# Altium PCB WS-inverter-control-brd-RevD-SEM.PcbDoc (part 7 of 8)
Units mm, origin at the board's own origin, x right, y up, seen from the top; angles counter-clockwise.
Board outline 270 x 105.92 mm, 6 copper layers (Top Layer, Int1 (Sign), Int2 (PWR), Int3 (GND), Int4 (Sign), Bottom Layer), stack 1.509 mm thick; 709 components, 375 nets, 2377 pads, 1332 vias.
Unrouted connection lines stored in the file: 55.
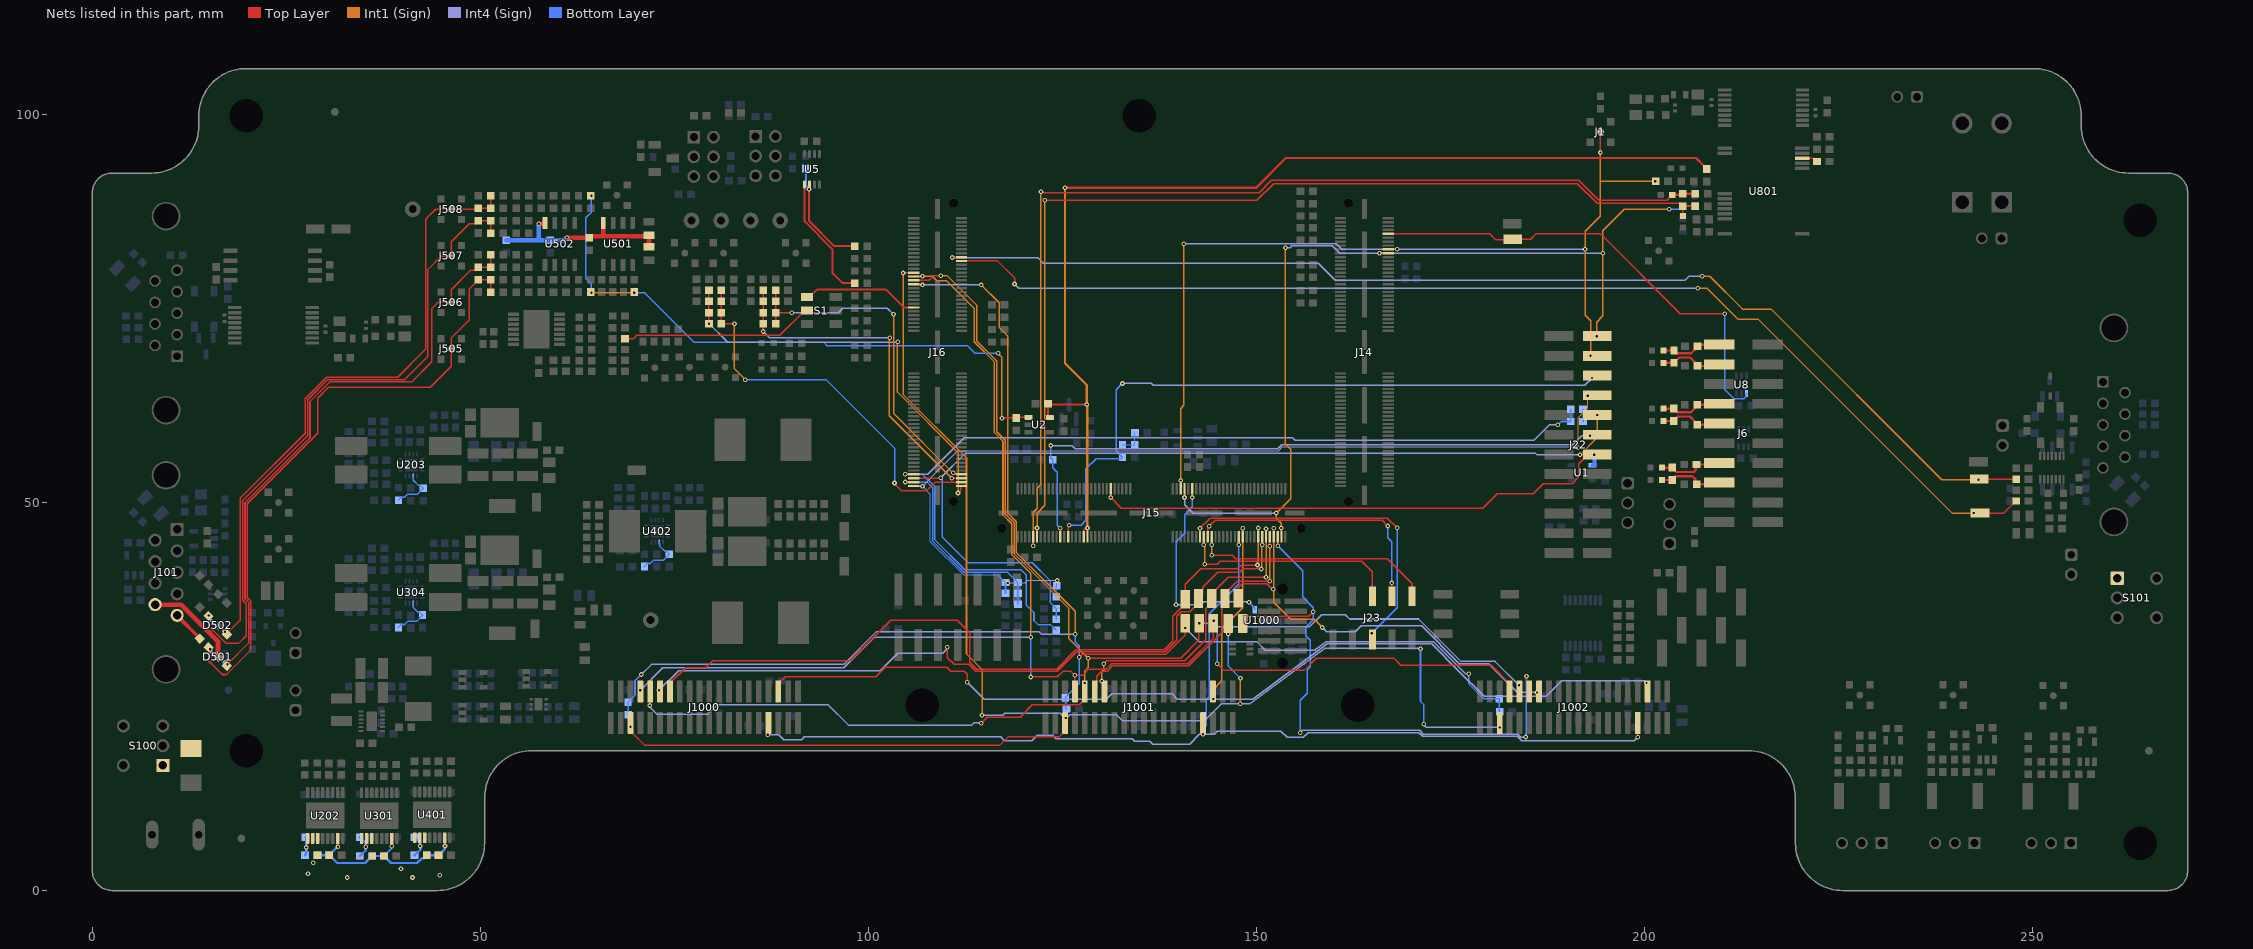
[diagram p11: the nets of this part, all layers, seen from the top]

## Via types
v1: diameter 0.6, hole 0.3, Top Layer to Bottom Layer, tented both sides, 1302 vias
v2: diameter 0.5, hole 0.2, Top Layer to Bottom Layer, 17 vias
v3: diameter 0.6, hole 0.3, Top Layer to Bottom Layer, 12 vias
v4: diameter 0.8, hole 0.5, Top Layer to Bottom Layer, tented both sides, 1 vias

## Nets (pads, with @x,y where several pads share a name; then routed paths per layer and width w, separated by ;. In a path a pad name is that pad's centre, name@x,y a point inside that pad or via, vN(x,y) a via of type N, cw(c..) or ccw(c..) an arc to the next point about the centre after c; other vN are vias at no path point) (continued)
Power_EN_HS: J15.23 J1000.36 J1001.36 J1002.36 | length 148.5
  Top Layer w0.18: J1000.36@88.399,25.653 88.399,26.681 89.265,27.546 100.953,27.546 102.197,28.79 110.09,28.79 110.633,28.246 112.333,28.246 112.741,27.838 v1(112.741,26.818) ; J1001.36@144.399,25.653 144.399,24.699 v1(144.422,24.676) ; J15.23@148.233,45.585 v1(148.233,46.67) ; v1(200.256,26.736) J1002.36@200.337,26.655
  Int1 (Sign) w0.18: v1(144.422,24.676) 144.422,25.899 145.543,27.021 145.543,33.726 148.233,36.416 v1(148.233,46.67)
  Int4 (Sign) w0.18: v1(112.741,26.818) 112.762,26.818 114.943,24.636 130.637,24.636 131.337,25.336 139.143,25.336 139.803,24.676 v1(144.422,24.676) 149.511,24.676 159.108,31.776 172.593,31.776 176.023,28.346 176.033,28.346 179.364,25.016 187.348,25.016 189.368,27.036 199.956,27.036 v1(200.256,26.736)
Power_EN_LoadSW: R237.1 R241.2 R302.1 R306.2 R405.1 R417.2 U202.7 U301.7 U401.7 | length 24.6
  Top Layer w0.2: v1@31.634,5.646 v1(31.643,5.636) ; U202.7@31.634,6.113 31.659,6.138 U202.7@31.661,6.138 ; U401.7@45.425,6.793 U401.7@45.434,6.784 ; v1@45.434,5.745 v1(45.443,5.736)
  Top Layer w0.3: v1@31.634,5.646 U202.7@31.634,6.113 ; v1(38.583,5.686) U301.7@38.582,6.693 ; v1@45.434,5.745 U401.7@45.434,6.784
  Bottom Layer w0.2: R306.2@37.568,4.443 37.593,4.443 38.583,5.432 v1(38.583,5.686)
  Bottom Layer w0.3: R237.1@29,4.563 R241.2@30.525,4.563 ; v1(31.643,5.636) 31.598,5.636 R241.2@30.525,4.563 ; R306.2@37.568,4.443 R302.1@36.068,4.443 36.043,4.443 35.137,3.536 31.551,3.536 R241.2@30.525,4.563 ; R306.2@37.593,4.443 38.5,3.536 41.843,3.536 42.477,4.17 42.727,4.17 R405.1@43.1,4.543 44.625,4.543 45.386,5.304 45.386,5.679 v1(45.443,5.736)
Power_EN_LS: J15.25 J1000.33 J1001.33 J1002.33 | length 147.6
  Top Layer w0.18: v1(87.045,20.066) 87.045,21.505 J1000.33@87.129,21.588 ; v1(143.116,20.134) 143.129,20.147 J1001.33@143.129,21.588 ; J15.25@147.733,45.585 147.738,45.58 147.738,44.541 v1(147.743,44.536) ; J1002.33@199.129,21.588 199.143,21.574 v1(199.143,19.736)
  Int4 (Sign) w0.18: v1(87.045,20.066) 88.477,20.066 89.091,19.451 91.417,19.451 91.762,19.796 117.05,19.796 117.53,19.316 121.033,19.316 121.728,20.011 123.788,20.011 124.234,19.565 134.015,19.565 134.343,19.236 136.252,19.236 136.619,18.869 141.386,18.869 142.651,20.134 v1(143.116,20.134) 144.541,20.134 144.954,20.547 153.133,20.547 153.943,19.736 156.043,19.736 156.655,20.348 170.94,20.348 171.411,19.876 183.581,19.876 184.184,19.273 198.68,19.273 v1(199.143,19.736)
  Bottom Layer w0.18: v1(143.116,20.134) 143.116,20.903 143.512,21.3 143.512,24.505 143.945,24.938 143.945,35.676 147.743,39.475 v1(147.743,44.536)
Power_Good: J15.50 U1000.4 | length 26.7
  Top Layer w0.18: v1(141.733,50.653) J15.50@141.733,51.757
  Int4 (Sign) w0.18: v1(139.643,36.836) 142.795,36.836 143.195,37.236 148.83,37.236 148.93,37.136 v1(149.043,37.136)
  Bottom Layer w0.18: v1(139.643,36.836) 139.643,44.959 140.743,46.059 140.743,46.494 140.743,46.9 140.743,48.443 141.733,49.433 v1(141.733,50.653) ; v1(149.043,37.136) 149.046,37.136 149.794,36.388 U1000.4@149.794,36.188
PWM1_H: J15.15 J1000.14 TP1.1 | length 99.8
  Top Layer w0.18: J1000.14@74.429,25.653 74.429,26.681 76.44,28.692 79.034,28.692 79.938,29.596 97.649,29.596 102.863,34.81 111.469,34.81 113.053,33.227 113.053,29.442 113.959,28.536 124.247,28.536 126.727,31.016 138.123,31.016 139.243,32.136 139.243,35.336 140.843,36.936 TP1.1@140.843,37.536 140.843,39.436 142.843,41.436 147.543,41.436 148.043,41.936 v1(150.143,41.936) ; J15.15@150.233,45.585 150.243,45.595 150.243,46.711 v1(150.254,46.721)
  Int1 (Sign) w0.18: v1(150.143,41.936) 150.153,41.946 150.153,42.506 150.243,42.596 150.243,46.711 v1(150.254,46.721)
PWM1_L: J15.13 J1000.12 TP2.1 | length 94.9
  Top Layer w0.18: v1(73.007,25.81) 73.143,25.947 J1000.12@73.143,26.236 ; v1(110.173,31.331) 110.173,30.007 111.043,29.136 112.912,29.136 113.812,28.236 124.343,28.236 126.843,30.736 138.243,30.736 139.743,32.236 139.743,35.365 140.305,35.926 141.433,35.926 142.543,37.036 TP2.1@142.543,37.636 143.053,38.146 143.053,39.073 145.016,41.036 147.871,41.036 148.271,41.436 v1(150.643,41.436) ; J15.13@150.733,45.585 150.738,45.58 150.738,44.541 v1(150.743,44.536)
  Int1 (Sign) w0.18: v1(150.643,41.436) 150.693,41.486 150.693,44.486 v1(150.743,44.536)
  Int4 (Sign) w0.18: v1(73.007,25.81) 75.533,28.336 101.539,28.336 103.797,30.594 109.556,30.594 110.01,31.048 110.01,31.054 110.173,31.217 v1(110.173,31.331)
PWM2_H: J15.11 J1001.14 TP3.1 | length 39.7
  Top Layer w0.18: v1(130.059,26.999) 130.429,26.629 J1001.14@130.429,25.653 ; v1(130.343,29.236) 130.703,29.596 140.782,29.596 143.487,32.301 143.487,36.28 144.243,37.036 144.243,38.236 146.38,40.373 v1(151.24,40.373)
  Top Layer w0.19: J15.11@151.233,45.585 151.238,45.59 151.238,46.631 v1(151.243,46.636)
  Int1 (Sign) w0.18: v1(130.059,26.999) 130.059,28.109 130.343,28.393 v1(130.343,29.236) ; v1(151.24,40.373) 151.243,40.376 151.243,42.558 151.243,44.549 v1(151.243,46.636)
PWM2_L: J15.9 J1001.12 TP4.1 | length 37.3
  Top Layer w0.18: J1001.12@129.159,25.653 129.439,25.934 129.439,27.632 130.053,28.246 130.753,28.246 131.453,28.946 141.263,28.946 145.543,33.226 145.543,37.236 TP4.1@145.943,37.636 ; TP4.1@145.943,38.236 147.556,39.849 v1(151.729,39.849) ; v1(151.733,44.346) J15.9@151.733,45.585
  Int1 (Sign) w0.18: v1(151.729,39.849) 151.733,39.854 v1(151.733,44.346)
PWM3_H: J15.7 J1002.14 TP5.1 | length 56.8
  Top Layer w0.18: TP5.1@147.65,37.678 147.656,37.684 147.656,39.043 148.15,39.536 151.336,39.536 152.064,38.809 v1(152.172,38.809) ; J15.7@152.233,45.585 v1(152.233,46.669) ; v1(186.149,25.522) 186.297,25.522 J1002.14@186.429,25.653
  Int1 (Sign) w0.18: v1@152.153,38.79 152.233,38.87 v1(152.233,46.669) ; v1(152.172,38.809) 152.228,38.753 152.228,37.148 154.439,34.936 157.464,34.936 v1(158.504,33.896)
  Int4 (Sign) w0.18: v1(158.504,33.896) 159.064,33.336 162.73,33.336 163.5,34.106 171.273,34.106 176.162,29.218 179.962,29.218 183.63,25.549 186.122,25.549 v1(186.149,25.522)
PWM3_L: J15.5 J1002.12 TP6.1 | length 78.2
  Top Layer w0.18: TP6.1@148.23,34.41 148.23,35.352 148.234,35.357 156.764,35.357 v1(157.343,35.936) ; J15.5@152.733,45.585 152.738,45.58 152.738,44.441 v1(152.743,44.436) ; v1(184.808,27.625) 184.808,27.032 185.159,26.681 J1002.12@185.159,25.653
  Int4 (Sign) w0.18: v1(155.643,20.336) 155.935,20.628 171.056,20.628 171.527,20.156 183.697,20.156 184.074,19.779 v1(184.722,19.779)
  Bottom Layer w0.18: v1(152.743,44.436) 155.943,41.236 155.943,37.836 157.343,36.436 v1(157.343,35.936) 157.343,34.871 156.379,33.906 156.379,32.833 156.951,32.26 156.951,28.83 156.54,28.419 156.54,25.433 155.643,24.536 v1(155.643,20.336) ; v1(184.722,19.779) 184.765,19.822 184.765,27.582 v1(184.808,27.625)
RES2_COS_1: C522.1 C524.2 J16.119 R555.1 R557.2 | length 53.5
  Top Layer w0.2: v1(79.45,73.053) R557.2@79.45,74.453 R555.1@79.45,77.353 ; v1(111.542,51.226) 111.909,51.593 111.909,52.069 111.962,52.122 J16.119@112.01,52.122
  Int1 (Sign) w0.2: v1(103.787,70.731) 103.743,70.687 103.743,64.231 111.581,56.393 111.581,51.265 v1(111.542,51.226)
  Int4 (Sign) w0.2: v1(79.45,73.053) 81.867,70.636 v1@103.743,70.636
RES2_COS_1_N: C524.1 C525.2 J16.117 R557.1 R559.2 | length 50.7
  Top Layer w0.2: R559.2@81.05,77.353 C525.2@81.05,75.953 R557.1@81.05,74.453 C524.1@81.05,73.053 v1(82.742,73.053) ; v1(103.371,52.507) 103.371,52.409 104.256,51.523 107.49,51.523 108.589,52.622 J16.117@112.01,52.622
  Int1 (Sign) w0.2: v1(82.742,73.053) 82.742,67.238 v1(84.143,65.836)
  Bottom Layer w0.2: v1(84.143,65.836) 94.543,65.836 103.371,57.009 v1(103.371,52.507)
RES2_SIN_1: C521.1 C523.2 J16.115 R554.1 R556.2 | length 44.7
  Top Layer w0.2: v1(86.443,72.036) 86.443,73.046 C523.2@86.45,73.053 R556.2@86.45,74.453 C521.1@86.45,75.953 R554.1@86.45,77.353 ; v1(110.743,53.136) 110.758,53.122 J16.115@112.01,53.122
  Int1 (Sign) w0.2: v1(102.743,71.236) 102.703,71.197 102.703,61.176 v1(110.743,53.136)
  Int4 (Sign) w0.2: v1(86.443,72.036) 87.243,71.236 v1(102.743,71.236)
RES2_SIN_1_N: C523.1 C526.2 J16.113 R556.1 R558.2 | length 44.9
  Top Layer w0.2: C523.1@88.05,73.053 R556.1@88.05,74.453 ; R558.2@88.05,77.353 C526.2@88.05,75.953 R556.1@88.05,74.453 ; v1(90.143,74.436) 90.127,74.453 R556.1@88.05,74.453 ; v1(110.916,53.815) 111.025,53.815 111.165,53.674 111.958,53.674 J16.113@112.01,53.622
  Int1 (Sign) w0.2: v1(103.243,74.236) 103.243,61.488 v1(110.916,53.815) v1@110.874,53.772
  Int4 (Sign) w0.2: v1(90.143,74.436) 96.101,74.436 96.701,75.036 102.443,75.036 v1(103.243,74.236)
RES_COS: C519.2 C530.2 J16.116 J22.10 R547.2 R568.2 | length 126.1
  Top Layer w0.2: J16.116@105.838,53.122 105.865,53.148 109.312,53.148 v1(109.338,53.175) ; v1(193.903,61.276) J22.10@193.943,61.276
  Int1 (Sign) w0.2: v1(191.703,56.136) 193.903,58.336 v1(193.903,61.276)
  Int4 (Sign) w0.2: v1(109.338,53.175) 112.528,56.365 185.915,56.365 186.143,56.136 v1(191.703,56.136)
  Bottom Layer w0.2: v1@109.338,53.169 109.338,53.066 109.543,52.861 109.543,45.536 112.843,42.236 121.121,42.236 123.458,39.899 123.458,37.076 124.193,36.342 C519.2@124.218,36.342 R547.2@124.218,34.942 ; R568.2@192.093,60.436 192.093,61.161 ; C530.2@192.093,62.036 192.093,61.161 ; v1(193.903,61.276) 192.208,61.276 192.093,61.161
RES_COS_N: C530.1 J16.114 R568.1 R569.2 | length 126.2
  Top Layer w0.2: v1(104.743,53.636) 104.75,53.629 105.835,53.629 J16.114@105.84,53.624
  Int4 (Sign) w0.2: v1(104.743,53.636) 107.647,53.636 112.368,58.357 154.647,58.357 154.99,58.014 185.764,58.014 187.787,60.036 v1(188.843,60.036)
  Bottom Layer w0.2: v1(104.743,53.636) 104.767,53.612 106.969,53.612 107.645,52.936 107.667,52.936 108.443,52.161 108.443,52.152 108.577,52.019 108.577,45.178 112.419,41.336 119.657,41.336 120.345,40.648 120.345,36.79 121.343,35.792 121.343,34.793 121.869,34.267 123.468,34.267 124.193,33.542 R569.2@124.218,33.542 ; v1(188.843,60.036) 188.892,60.036 189.292,60.436 R568.1@190.493,60.436 C530.1@190.493,62.036
RES_EXC: J15.97 J22.12 R513.1 | length 83.7
  Top Layer w0.18: J15.97@124.733,45.585 v1(124.733,46.687) ; v1(192.988,58.599) 193.126,58.736 J22.12@193.943,58.736
  Int4 (Sign) w0.18: v1(123.48,57.34) 126.218,57.34 126.64,56.918 152.743,56.918 153.249,57.424 190.762,57.424 191.937,58.599 v1(192.988,58.599)
  Bottom Layer w0.18: v1(123.48,57.34) 123.48,55.751 R513.1@123.744,55.487 123.744,54.498 124.343,53.899 124.343,47.077 v1(124.733,46.687)
RES_EXC_OUT_PWM: R550.1 S1.5 | length 25
  Top Layer w0.2: R550.1@68.638,71.111 69.736,71.111 70.161,71.536 71.703,71.536 74.54,71.536 88.593,71.536 91.793,74.736 S1.5@92.093,74.736
"RES_EXC_OUT_PWM_AFTER SWITCH_16": J16.48 S1.6 | length 15.1
  Top Layer w0.25: S1.6@92.093,76.486 92.393,76.486 93.343,77.436 102.271,77.436 104.558,75.149 105.811,75.149 J16.48@105.838,75.122
RES_SIN: C512.2 C527.2 J16.120 J22.8 R528.2 R563.2 | length 124.8
  Top Layer w0.16: J16.120@105.838,52.122 105.845,52.115 106.967,52.115 v1(106.974,52.108)
  Int1 (Sign) w0.16: v1(191.443,57.036) 191.443,60.911 192.711,62.179 v1(192.711,63.76)
  Int4 (Sign) w0.16: v1(106.974,52.108) 109.207,54.34 111.514,56.648 152.855,56.648 153.361,57.154 191.129,57.154 191.163,57.121 191.359,57.121 v1(191.443,57.036) ; v1(117.94,39.637) 120.201,39.637 120.513,39.949 v1(124.322,39.949)
  Bottom Layer w0.16: v1(106.974,52.108) 107.997,51.085 107.997,44.938 112.255,40.68 116.675,40.68 C527.2@117.668,39.686 ; C512.2@124.218,37.842 124.238,37.862 124.238,39.238 R528.2@124.258,39.258 124.258,39.885 v1(124.322,39.949)
  Bottom Layer w0.2: R563.2@117.668,38.286 C527.2@117.668,39.686 117.89,39.686 v1(117.94,39.637)
RES_SIN_N: C527.1 J16.118 R563.1 R564.2 | length 27.8
  Top Layer w0.2: v1(104.743,52.636) 104.75,52.629 105.831,52.629 J16.118@105.838,52.622
  Bottom Layer w0.2: v1(104.743,52.636) 107.543,52.636 108.143,52.036 108.143,52.028 108.277,51.894 108.277,45.054 112.295,41.036 117.893,41.036 119.243,39.686 C527.1@119.268,39.686 R563.1@119.268,38.286 R564.2@119.268,36.886
RX: J16.23 R609.1 TP604.1 | length 149.6
  Top Layer w0.2: J16.23@112.058,81.122 112.065,81.129 116.65,81.129 118.835,78.945 v1(118.835,78.146) ; TP604.1@243.243,48.636 246.311,48.636 247.875,50.2 R609.1@247.9,50.2
  Int1 (Sign) w0.2: v1(206.864,77.604) 208.071,77.604 212.039,73.636 214.643,73.636 239.643,48.636 v1(242.443,48.636)
  Int4 (Sign) w0.2: v1(118.835,78.146) 119.376,77.604 v1(206.864,77.604)
Safety_OR_gate_out: J15.72 J22.14 U1.4 | length 69.8
  Top Layer w0.18: J15.72@131.233,51.757 v1(131.233,50.65) 132.607,49.276 179.171,49.276 181.031,51.136 185.643,51.136 186.943,52.436 190.684,52.436 191.553,53.305 191.553,54.009 191.559,54.016 191.559,55.017 192.738,56.196 193.543,56.196 J22.14@193.943,56.196
  Bottom Layer w0.5: U1.4@193.318,54.786 193.493,54.786 193.543,54.836 v1(193.543,56.136)
SIN+_1: J101.9 R526.2 | length 12.1
  Top Layer w0.6: J101.9@8.08,36.845 11.437,36.845 16.182,32.1 16.182,30.118 R526.2@16.2,30.1
SIN-_1: J101.5 R521.2 | length 4.2
  Top Layer w0.5: J101.5@10.92,35.46 10.92,35.42 13.834,32.506 R521.2@13.834,32.466
SPIA_CLK_16: J15.43 J23.5 | length 29.1
  Top Layer w0.18: v1(143.233,44.546) J15.43@143.233,45.585 ; v1(143.326,42.049) 144.95,42.049 145.349,42.448 163.559,42.448 164.943,41.064 J23.5@164.943,37.93
  Int1 (Sign) w0.18: v1(143.233,44.546) 143.233,44.433 143.326,44.34 v1(143.326,42.049)
SPIA_SIMO_16: J15.39 J23.1 | length 31.3
  Top Layer w0.18: J15.39@144.233,45.585 144.238,45.58 144.238,44.541 v1(144.243,44.536) ; v1(144.258,43.191) 146.871,43.191 147.335,42.728 166.883,42.728 170.023,39.587 J23.1@170.023,37.93
  Int1 (Sign) w0.18: v1(144.243,44.536) 144.251,44.529 144.251,43.199 v1(144.258,43.191)
SPIA_SOMI_16: J15.41 J23.3 | length 34.4
  Top Layer w0.18: J15.41@143.733,45.585 143.738,45.59 143.738,46.619 143.932,46.813 143.932,46.98 144.665,47.714 166.196,47.714 v1(166.943,46.966) ; v1(167.443,39.636) 167.443,37.97 J23.3@167.483,37.93
  Bottom Layer w0.18: v1(166.943,46.966) 166.943,45.458 167.443,44.958 v1(167.443,39.636)
  other v1: 143.932,46.926
SPIA_STE_16: J15.45 J23.6 | length 42.6
  Top Layer w0.18: J15.45@142.733,45.585 142.728,45.59 142.728,46.69 v1(142.723,46.695) 144.021,47.994 166.886,47.994 v1(168.143,46.736)
  Bottom Layer w0.18: v1(164.843,33.136) 168.143,36.436 v1(168.143,46.736)
TP_COS+_5: D502.6 J508.1 R540.1 R544.2 R545.1 R549.2 | length 80.5
  Top Layer w0.2: R545.1@17.339,33.126 v1(17.1,33.365) 17.572,33.365 19.073,34.866 19.073,50.566 27.443,58.936 27.443,63.361 30.219,66.136 39.343,66.136 42.943,69.736 42.943,86.502 44.237,87.795 J508.1@46.254,87.795 49.622,87.795 R549.2@49.738,87.911 R540.1@51.338,87.911 R544.2@51.338,89.511
  Bottom Layer w0.2: v1(17.1,33.365) D502.6@17.1,33.509
TP_COS-_5: D502.3 J507.1 R533.1 R537.2 R538.1 R540.2 | length 84.8
  Top Layer w0.2: v1(14.985,35.447) 14.983,35.445 14.983,34.826 14.985,34.825 14.985,34.095 17.243,31.836 18.843,31.836 19.837,32.83 19.837,36.942 19.373,37.406 19.373,50.266 27.743,58.636 27.743,63.236 30.343,65.836 40.243,65.836 43.243,68.836 43.243,80.036 44.943,81.736 44.973,81.766 46.224,81.766 J507.1@46.254,81.795 46.254,83.607 48.558,85.911 49.363,85.911 49.738,86.286 R533.1@49.738,86.311 R540.2@51.338,86.311 R537.2@51.338,84.711
  Bottom Layer w0.2: v1(14.985,35.447) 15.062,35.37 15.062,34.919 15.172,34.809 D502.3@15.2,34.809
TP_SIN+_5: D501.6 J506.1 R522.1 R525.2 R526.1 R530.2 | length 76.4
  Top Layer w0.2: R526.1@17.41,28.926 v1(17.41,29.158) 20.137,31.885 20.137,37.142 19.673,37.606 19.673,49.966 28.043,58.336 28.043,63.003 30.576,65.536 41.143,65.536 43.743,68.136 43.743,74.991 44.547,75.795 J506.1@46.254,75.795 46.254,77.423 48.742,79.911 49.363,79.911 49.738,80.286 R530.2@49.738,80.311 R522.1@51.338,80.311 R525.2@51.338,81.911
  Bottom Layer w0.2: D501.6@17.1,29.469 v1(17.41,29.158)
TP_SIN-_5: D501.3 J505.1 R515.1 R520.2 R521.1 R522.2 | length 80.4
  Top Layer w0.2: R521.1@14.983,31.1 14.983,29.596 16.743,27.836 17.293,27.836 20.437,30.98 20.437,37.267 19.973,37.731 19.973,49.842 29.043,58.912 29.043,63.437 30.442,64.836 43.543,64.836 46.248,67.542 46.248,69.79 J505.1@46.254,69.795 46.254,71.204 48.539,73.489 48.539,77.487 49.738,78.686 R515.1@49.738,78.711 R522.2@51.338,78.711 R520.2@51.338,77.111
  Bottom Layer w0.2: D501.3@15.2,30.769 v1(15.2,31.1)
TX: J16.21 R604.1 TP600.1 | length 150.6
  Top Layer w0.2: v1(110.825,81.566) 110.853,81.594 111.982,81.594 J16.21@112.01,81.622 ; v1(243.043,52.936) TP600.1@243.143,53.036 243.18,53 R604.1@247.9,53
  Int1 (Sign) w0.2: v1(207.429,79.144) 208.409,79.144 212.635,74.918 216.322,74.918 238.303,52.936 v1(243.043,52.936)
  Int4 (Sign) w0.2: v1(110.825,81.566) 121.814,81.566 122.543,80.836 157.955,80.836 160.158,78.634 205.237,78.634 205.747,79.144 v1(207.429,79.144)
U_1_N: "C1_Phase A.1" "C8_Phase A.2" "R1_Phase A.2" J6.14 | length 8.1
  Top Layer w0.3: 202.264,54.492 202.268,54.495 203.569,54.495 203.573,54.499 ; 203.573,54.474 204.11,53.936 206.373,53.936 206.623,54.186 206.623,54.574 206.948,54.899 209.453,54.899 J6.14@209.473,54.879
U_1_P: "C1_Phase A.2" "C14_Phase A.2" "R3_Phase A.2" J6.13 | length 8.1
  Top Layer w0.3: 202.264,52.892 202.268,52.895 203.569,52.895 203.573,52.899 203.573,52.924 204.031,53.382 206.197,53.382 206.541,53.039 206.541,52.69 206.866,52.365 209.447,52.365 J6.13@209.473,52.339
UART1_LDC_RX: R27.2 R55.1 U5.6 | length 14.8
  Top Layer w0.25: v1(92.356,90.363) 92.356,86.273 95.592,83.036 R27.2@98.243,83.036 ; v1@92.39,90.363 92.39,90.933 U5.6@92.418,90.961
  Bottom Layer w0.25: R55.1@91.943,93.036 91.943,90.87 92.356,90.458 v1(92.356,90.363)
UART2_LDC_TX: R30.2 U5.5 | length 16.3
  Top Layer w0.25: U5.5@91.768,90.961 91.768,86.224 95.4,82.592 95.4,79.531 96.671,78.26 98.22,78.26 R30.2@98.243,78.236
UCC5890_CLK: J16.34 J1000.10 J1001.10 J1002.10 TP9.1 | length 191.6
  Top Layer w0.18: v1(114.543,21.536) 115.343,22.336 119.543,22.336 121.143,23.936 127.199,23.936 127.889,24.626 J1001.10@127.889,25.653 127.889,26.725 v1(127.9,26.736)
  Top Layer w0.2: v1(71.843,23.836) 71.843,25.608 J1000.10@71.889,25.653 ; J16.34@105.838,78.622 107.769,78.622 108.383,79.236 v1(109.343,79.236) ; v1(128.343,29.936) 140.243,29.936 142.543,32.236 142.543,34.336 v1(142.643,34.436)
  Int1 (Sign) w0.2: v1(109.343,79.236) 110.143,79.236 113.943,75.436 113.943,70.836 116.543,68.236 116.543,59.129 117.643,58.029 117.643,48.512 118.768,47.387 118.768,43.424 125.843,36.349 125.843,32.436 v1(128.343,29.936) 128.343,28.732 127.9,28.288 v1(127.9,26.736)
  Int4 (Sign) w0.2: v1(71.843,23.836) 71.92,23.76 71.92,23.56 72.743,22.736 79.343,22.736 80.543,23.936 94.805,23.936 97.425,21.317 113.324,21.317 113.62,21.613 114.467,21.613 v1(114.543,21.536) ; v1(142.643,34.436) 142.672,34.466 143.623,34.466 144.076,34.012 156.885,34.012 158.409,35.536 161.448,35.536 161.998,34.986 170.893,34.986 176.353,29.527 180.753,29.527 v1(183.843,26.436)
UCC5890_nCS: J16.36 R1000.2 R1001.2 R1002.2 R1003.1 R1004.1 R1005.1 TP10.1 | length 198
  Top Layer w0.2: J16.36@105.838,78.122 105.881,78.079 106.931,78.079 v1(106.974,78.036) ; v1(127.177,30.07) 127.543,30.436 138.343,30.436 138.353,30.446 138.363,30.446 140.843,32.926 TP10.1@140.843,33.838 ; TP10.1@140.843,34.426 TP10.1@140.843,34.936 ; v1(140.845,33.838) TP10.1@140.845,34.426
  Int1 (Sign) w0.2: v1(114.543,78.036) 116.853,75.726 116.853,72.534 117.943,71.444 117.943,48.636 119.068,47.511 119.068,43.548 126.643,35.973 v1@126.643,33.037
  Int4 (Sign) w0.2: v1(70.743,27.836) 72.043,29.136 96.832,29.136 101.057,33.361 121.965,33.361 122.29,33.036 v1(126.643,33.036) ; v1(106.974,78.036) v1(114.543,78.036) ; v1(140.845,33.838) 142.646,32.036 150.073,32.036 151.145,30.965 157.458,30.965 157.524,30.965 157.577,31.004 158.918,31.997 158.988,32.066 172.813,32.066 176.919,27.961 177.319,27.961 v1(177.343,27.936)
  Bottom Layer w0.2: R1003.1@69.043,22.636 69.031,22.649 R1000.2@69.031,24.256 69.031,24.281 69.925,25.175 69.925,27.018 v1(70.743,27.836) ; R1004.1@125.543,23.386 125.433,23.496 125.433,24.769 R1001.2@125.349,24.854 127.177,26.682 v1(127.177,30.07) 127.177,31.473 126.643,32.008 v1(126.643,33.036) ; v1(177.343,27.936) 177.343,26.682 179.321,24.703 181.268,24.703 181.295,24.676 181.295,23.085 R1005.1@181.343,23.036
UCC5890_SDI: J16.30 J1000.5 J1001.5 J1002.5 TP7.1 | length 213.4
  Top Layer w0.2: v1(69.349,21.088) 69.619,20.818 69.619,20.261 71.143,18.736 85.433,18.736 116.953,18.736 118.047,19.831 124.637,19.831 125.079,20.272 125.079,21.318 J1001.5@125.349,21.588 125.349,22.142 v1(125.443,22.236) ; v1(104.47,79.565) 104.527,79.622 J16.30@105.838,79.622 ; v1(146.364,33.064) TP7.1@146.364,34.415
  Int1 (Sign) w0.2: v1(104.47,79.565) 104.47,63.928 112.643,55.755 112.643,30.48 114.643,28.48 v1(114.643,22.568) ; v1(147.927,24.052) 147.935,24.06 147.935,27.328 v1(147.943,27.336)
  Int4 (Sign) w0.2: v1(114.643,22.568) 117.312,22.568 117.58,22.836 124.735,22.836 v1@125.335,22.236 ; v1@125.551,22.236 125.721,22.406 ; 125.722,22.406 125.952,22.636 131.96,22.636 132.7,21.897 143.355,21.897 145.51,24.052 149.089,24.052 149.155,24.052 149.208,24.092 158.839,31.216 171.063,31.216 v1(171.143,31.136) ; v1@171.688,21.203 171.875,21.016 v1(181.342,21.016)
  Bottom Layer w0.2: v1(146.364,33.064) 146.364,28.916 v1(147.943,27.336) ; v1(171.143,31.136) 171.143,24.369 171.543,23.969 v1(171.543,21.436)
UCC5890_SDO: J16.32 J1000.8 J1001.8 J1002.8 TP8.1 | length 190.4
  Top Layer w0.2: J16.32@105.838,79.122 105.846,79.13 106.966,79.13 v1(106.974,79.138) ; v1(120.933,27.523) 120.946,27.536 124.343,27.536 125.043,28.236 126.109,28.236 v1(126.586,27.76) ; J1001.8@126.619,25.653 126.586,25.687 v1(126.586,27.76) ; TP8.1@144.458,34.436 144.458,32.551 141.143,29.236 131.333,29.236 130.633,28.536 128.442,28.536 127.665,27.76 v1(126.586,27.76) ; v1(144.49,34.773) 144.713,34.996 TP8.1@144.91,34.996 ; v1(144.943,29.229) 144.951,29.229 145.774,28.405 156.192,28.405 157.715,29.928 167.718,29.928 168.61,29.036 180.263,29.036 182.619,26.681 J1002.8@182.619,25.653
  Int1 (Sign) w0.2: v1(106.974,79.138) 108.242,79.138 108.796,78.584 110.072,78.584 113.643,75.012 113.643,70.712 116.243,68.112 116.243,59.005 117.343,57.905 117.343,48.388 118.468,47.263 118.468,43.3 120.933,40.835 v1(120.933,32.622)
  Int4 (Sign) w0.2: v1(70.619,25.812) 73.499,28.692 96.812,28.692 100.742,32.622 104.715,32.622 104.719,32.626 120.085,32.626 120.09,32.622 v1(120.933,32.622)
  Bottom Layer w0.2: v1(120.933,27.523) v1(120.933,32.622) ; v1(144.49,34.773) 144.49,34.761 144.908,34.343 144.908,34.341 144.943,34.306 v1(144.943,29.229)
V_1_N: "C1_Phase C.1" "C8_Phase C.2" "R1_Phase C.2" J6.17 | length 7.5
  Top Layer w0.3: 202.464,62.092 202.468,62.095 203.769,62.095 203.773,62.099 203.773,62.074 204.21,61.636 206.01,61.636 206.623,62.249 206.623,62.274 206.948,62.599 J6.17@209.373,62.599
V_1_P: "C1_Phase C.2" "C14_Phase C.2" "R3_Phase C.2" J6.16 | length 8
  Top Layer w0.3: 202.464,60.492 202.468,60.495 203.769,60.495 203.773,60.499 203.773,60.524 204.331,61.082 205.889,61.082 206.623,60.349 206.623,60.324 206.948,59.999 209.466,59.999 J6.16@209.643,60.176
VCC: C420.2 R429.2 U402.2 | length 6.1
  Bottom Layer w0.2: R429.2@71.143,41.736 71.143,41.761 71.518,42.136 71.888,42.136 72.288,42.536 73.568,42.536 74.343,43.311 74.343,43.36 73.968,43.735 73.745,43.735 73.093,44.386 73.093,44.672 73.07,44.695 73.07,44.88 U402.2@73.05,44.9
VCC-opamp: C516.1 C517.1 C518.1 R539.2 R541.2 U501.8 U502.8 | length 24.9
  Top Layer w0.6: v1(57.535,85.929) 58.333,85.929 U502.8@58.333,86.011 ; v1(61.143,84.136) 64.038,84.136 64.213,84.311 65.833,84.311 ; U501.8@65.833,86.011 65.833,84.311 ; R539.2@71.738,82.941 R541.2@71.738,84.431 71.618,84.311 65.833,84.311
  Bottom Layer w0.6: C517.1@53.325,83.779 57.535,83.779 ; v1(57.535,85.929) 57.535,83.779 ; v1(61.143,84.136) 60.786,83.779 C516.1@59.025,83.779 57.535,83.779
VCC_H: C229.2 R245.2 U203.2 | length 6.2
  Bottom Layer w0.2: R245.2@39.443,50.286 39.443,50.307 39.818,50.682 40.233,50.682 40.613,51.061 41.893,51.061 42.643,51.811 C229.2@42.643,51.836 42.276,52.204 42.014,52.204 41.35,52.868 U203.2@41.35,53.45
VCC_L: C330.2 R312.2 U304.2 | length 6
  Bottom Layer w0.2: R312.2@39.443,33.886 39.443,33.907 39.818,34.282 40.233,34.282 40.628,34.676 41.755,34.676 42.546,35.467 42.546,35.507 42.171,35.882 41.939,35.882 41.35,36.471 U304.2@41.35,37.05
VDC: J15.93 J22.6 R804.2 | length 87.1
  Top Layer w0.18: J15.93@125.733,45.585 125.733,46.801 125.889,46.956 v1(125.889,47.07)
  Int4 (Sign) w0.18: v1(132.743,65.336) 136.443,65.336 136.695,65.085 192.291,65.085 v1(193.243,66.036)
  Bottom Layer w0.18: v1@125.902,47.07 127.4,47.07 128.04,47.71 128.04,54.33 129.346,55.636 132.543,55.636 R804.2@132.743,55.836 132.743,55.861 131.943,56.661 131.943,64.536 v1(132.743,65.336)
Vdc_C: J14.102 J15.3 J15.54 J22.2 R11.2 | length 122.7
  Top Layer w0.18: v1(140.733,50.638) J15.54@140.733,51.757 ; v1(153.211,46.721) 153.222,46.71 153.222,45.596 J15.3@153.233,45.585 ; v1(165.865,82.109) 165.872,82.116 166.995,82.116 J14.102@167.001,82.122 ; v1(193.843,71.436) J22.2@193.943,71.436
  Int1 (Sign) w0.18: v1(153.211,46.721) 153.211,47.296 152.543,47.963 v1(152.543,48.636) 154.394,50.487 154.394,56.888 153.743,57.539 v1(153.743,82.836) ; v1(193.843,71.436) 193.843,73.236 194.643,74.036 v1(194.643,82.136) 194.643,85.036 197.402,87.795 v1(203.213,87.795)
  Int4 (Sign) w0.18: v1(140.733,50.638) 140.733,49.727 141.833,48.626 152.533,48.626 v1(152.543,48.636) ; v1(153.743,82.836) 154.34,82.836 154.56,83.056 159.767,83.056 160.715,82.109 v1(165.865,82.109) 165.879,82.123 194.63,82.123 v1(194.643,82.136)
  Bottom Layer w0.18: v1(203.213,87.795) 204.933,87.795 205.316,88.178 R11.2@206.55,88.178
  Bottom Layer w0.25: R11.2@206.51,88.219 R11.2@206.55,88.178
Vdc_D: J1.1 J14.104 J15.56 J22.4 R13.2 | length 122.8
  Top Layer w0.18: J15.56@140.233,51.757 v1(140.233,52.826) ; J14.104@167.001,82.622 167.008,82.629 168.136,82.629 v1(168.143,82.636) ; v1(193.056,68.896) J22.4@193.943,68.896 ; J1.1@194.323,97.756 194.326,97.754 194.326,95.102 v1(194.328,95.1)
  Int1 (Sign) w0.18: v1(140.233,52.826) 140.233,62.101 140.643,62.511 v1(140.643,83.336) ; v1(193.056,68.896) 193.056,73.424 192.343,74.136 v1(192.343,82.636) 192.343,84.936 194.285,86.878 194.285,91.378 ; v1(194.328,95.1) 194.285,95.056 194.285,91.378 ; v1(201.375,91.378) 194.285,91.378
  Int4 (Sign) w0.18: v1(140.643,83.336) 160.265,83.336 160.965,82.636 v1(168.143,82.636) v1(192.343,82.636)
VDC_diff_2: C16.1 R10.2 R804.1 | length 3.2
  Bottom Layer w0.16: R804.1@132.743,57.436 C16.1@134.343,57.436 R10.2@134.343,59.002
VDC_N: C3.1 C3d1.2 J15.111 R2.2 | length 133.6
  Top Layer w0.18: v1(121.233,44.446) J15.111@121.233,45.585 ; v1(122.233,90.046) 122.314,89.966 122.519,89.966 122.549,89.936 150.343,89.936 151.943,91.536 191.543,91.536 194.113,88.966 202.923,88.966 203.283,89.326 203.283,89.351 203.568,89.636 C3d1.2@203.593,89.636
  Top Layer w0.3: C3d1.2@203.593,89.636 204.809,89.636 C3.1@204.95,89.778 R2.2@206.55,89.778
  Int1 (Sign) w0.18: v1(121.233,44.446) 121.233,48.726 121.743,49.236 121.743,51.822 122.233,52.312 v1(122.233,90.046)
VDC_P: C3.2 C3d2.2 J15.109 R6.2 | length 130.9
  Top Layer w0.18: J15.109@121.733,45.585 v1(121.733,46.718) ; v1(122.743,88.961) 150.068,88.961 152.209,91.102 191.363,91.102 193.934,88.532 204.596,88.532 C3.2@204.95,88.178 ; C3d2.2@204.95,86.928 C3.2@204.95,88.178 ; R6.2@206.55,88.178 C3.2@204.95,88.178
  Int1 (Sign) w0.18: v1(121.733,46.718) 121.733,48.626 122.743,49.636 v1(122.743,88.961)
VIN_12V_1: C208.1 C209.1 C300.1 C301.1 C402.1 C404.1 D100.1 R236.2 R237.2 R301.2 R302.2 R402.2 R405.2 S100.1 S101.1 U202.1 U202.2 U202.3 U301.1 U301.2 U301.3 U401.1 U401.2 U401.3 | length 8.4
  Bottom Layer w0.3: R237.2@27.4,4.563 27.543,4.706 27.543,6.777 R236.2@27.457,6.863 ; R301.2@34.457,6.843 34.482,6.843 35.205,6.12 35.205,5.682 v1(35.243,5.644) 35.243,5.193 34.493,4.443 R302.2@34.468,4.443 ; R405.2@41.5,4.543 41.525,4.543 42.243,5.261 v1(42.243,5.736) 42.205,5.775 42.205,6.163 41.525,6.843 R402.2@41.5,6.843
  other v1: 32.853,1.676 41.253,1.676 44.753,1.976 27.782,2.144 39.77,2.794 28.453,3.576 27.543,5.536
Voc_tmcs: J14.112 TP_voc.1 U8.4 | length 61.8
  Top Layer w0.2: J14.112@167.001,84.622 180.058,84.622 180.843,83.836 182.943,83.836 TP_voc.1@183.043,83.936 185.343,83.936 186.029,84.622 194.337,84.622 204.623,74.336 v1(210.343,74.336)
  Bottom Layer w0.2: v1(210.343,74.336) 210.343,64.568 211.519,63.392 211.534,63.377 212.787,63.377 213.073,63.662 213.073,63.949 U8.4@213.173,64.049
VOUT_C_N: "C1_Phase B.1" "C8_Phase B.2" "R1_Phase B.2" J6.20 | length 8.1
  Top Layer w0.3: 202.464,69.592 203.814,69.592 203.814,69.567 204.139,69.242 204.309,69.242 204.315,69.236 206.043,69.236 206.593,69.786 206.593,69.811 206.918,70.136 ; 206.943,70.136 207.143,70.336 J6.20@209.643,70.336 J6.20@209.399,70.092
VOUT_C_P: "C1_Phase B.2" "C14_Phase B.2" "R3_Phase B.2" J6.19 | length 7.7
  Top Layer w0.3: 202.464,67.992 203.814,67.992 203.814,68.017 204.139,68.342 204.48,68.682 205.897,68.682 206.593,67.986 206.593,67.961 206.918,67.636 206.943,67.636 ; 207.048,67.599 207.073,67.599 209.453,67.599 J6.19@209.473,67.579
VREF: C7.1 J15.83 J15.85 R25.1 U2.5 | length 139.3
  Top Layer w0.18: J15.85@127.733,45.585 127.733,46.433 128.023,46.723 v1(128.233,46.723) ; J15.83@128.233,45.686 v1@128.233,46.7
  Top Layer w0.3: U2.5@123.385,60.961 123.318,60.961 123.143,61.136 C7.1@123.143,62.703 123.21,62.636 v1(128.143,62.636) ; v1(125.343,90.536) 149.943,90.536 153.792,94.385 206.643,94.385 207.7,93.328 207.725,93.328 208.05,93.003 R25.1@208.05,92.978
  Int1 (Sign) w0.3: v1(125.343,90.536) 125.343,67.936 128.143,65.136 v1(128.143,62.636) 128.195,62.585 128.195,46.761 v1(128.233,46.723)
VREF_1/2: C4.1 R516.1 R529.1 R548.1 U2.1 | length 81.2
  Top Layer w0.2: R529.1@64.238,77.111 v1(64.309,77.04) ; R548.1@64.238,89.586 v1(64.309,89.515) ; v1(69.834,77.04) R516.1@69.838,77.036 ; v1(117.21,60.836) 117.277,60.903 C4.1@119.043,60.903 119.102,60.961 U2.1@120.635,60.961 U2.1@120.543,61.053
  Int1 (Sign) w0.2: v1(64.309,77.04) v1(69.834,77.04) ; v1(116.743,69.236) 116.743,69.168 117.21,68.702 v1(117.21,60.836)
  Bottom Layer w0.2: v1(64.309,77.04) 64.309,78.133 63.581,78.861 63.581,86.686 64.309,87.415 v1(64.309,89.515) ; v1(69.834,77.04) 71.139,77.04 77.505,70.675 94.206,70.675 94.702,70.178 112.801,70.178 113.743,69.236 v1(116.743,69.236)
VSNS_9: C807.1 U801.4 | length 2.1
  Top Layer w0.25: U801.4@220.318,94.361 221.793,94.361 222.218,93.936 C807.1@222.243,93.936
pads on no net: FID1200.1 FID1201.1 FID1202.1 FID1203.1 FID1204.1 FID1205.1 J11.3 J11.11 J11.MH1 J11.MH2 J14.1 J14.2 J14.3 J14.4 J14.5 J14.6 J14.7 J14.8 J14.9 J14.10 J14.11 J14.12 J14.13 J14.14 J14.15 J14.16 J14.17 J14.18 J14.19 J14.20 J14.21 J14.22 J14.23 J14.24 J14.25 J14.26 J14.28 J14.29 J14.30 J14.31 J14.32 J14.33 J14.34 J14.35 J14.36 J14.37 J14.38 J14.39 J14.40 J14.41 J14.42 J14.43 J14.44 J14.45 J14.46 J14.47 J14.48 J14.49 J14.50 J14.51 J14.52 J14.53 J14.54 J14.55 J14.56 J14.57 J14.58 J14.59 J14.60 J14.61 J14.62 J14.63 J14.64 J14.65 J14.66 J14.67 J14.68 J14.69 J14.70 J14.71 J14.72 J14.73 J14.74 J14.75 J14.76 J14.77 J14.78 J14.79 J14.80 J14.81 J14.82 J14.83 J14.84 J14.85 J14.86 J14.88 J14.89 J14.90 J14.91 J14.92 J14.93 J14.94 J14.95 J14.96 J14.97 J14.98 J14.99 J14.101 J14.103 J14.107 J14.110 J14.116 J14.117 J14.119 J14.MH1 J14.MH2 J15.1 J15.27 J15.40 J15.42 J15.44 J15.46 J15.47 J15.58 J15.60 J15.62 J15.64 J15.66 J15.68 J15.75 J15.76 J15.79 J15.80 J15.81 J15.82 J15.84 J15.86 J15.87 J15.88 J15.89 J15.94 J15.98 J15.100 J15.106 J15.MH1 J15.MH2 J16.1 J16.2 J16.3 J16.4 J16.5 J16.6 J16.7 J16.8 J16.9 J16.10 J16.11 J16.12 J16.13 J16.14 J16.15 J16.16 J16.17 J16.18 J16.19 J16.20 J16.22 J16.24 J16.25 J16.27 J16.29 J16.31 J16.33 J16.35 J16.37 J16.38 J16.39 J16.40 J16.41 J16.42 J16.43 J16.44 J16.45 J16.47 J16.49 J16.51 J16.61 J16.62 J16.63 J16.64 J16.65 J16.66 J16.67 J16.68 J16.69 J16.70 J16.71 J16.72 J16.73 J16.74 J16.75 J16.76 J16.77 J16.78 J16.79 J16.80 J16.81 J16.82 J16.83 J16.84 J16.85 J16.86 J16.87 J16.88 J16.89 J16.90 J16.91 J16.92 J16.93 J16.94 J16.95 J16.96 J16.97 J16.98 J16.99 J16.100 J16.101 J16.102 J16.103 J16.104 J16.105 J16.106 J16.107 J16.108 J16.109 J16.110 J16.111 J16.112 J16.MH1 J16.MH2 J22.16 J22.18 J24.2 J24.6 J101.2 J102.1 J102.4 J102.6 J102.8 J103.1 J103.4 J103.6 LBL1200.0 S1.1 S1.2 S1.3 S2.3 S100.3 S100.4 S100.5 S101.3 S101.4 S101.5 U201.2 U202.4 U202.13 U202.17@30,9.663 U203.12 U203.15 U300.2 U301.4 U301.13 U301.17@36.957,9.643 U302.7 U302.11 U303.4 U304.12 U304.15 U305.2 U305.5 U305.7@57.5,23.55 U305.7@57.5,24.45 U401.4 U401.13 U401.17@43.8,9.743 U402.15 U500.7 U500.8 U501.7 U601.11 U603.8 U801.12 U801.13

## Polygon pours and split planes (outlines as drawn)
GND on Bottom Layer "BOTTOM_LAYER_GND_P462" (solid, remove dead copper, pour order 462): 26.643,105.918 26.643,58.921 23.219,55.496 0.039,55.496 0.039,-0.004 50.585,-0.004 50.585,9.542 59.579,18.536 219.539,18.536 219.539,-1.064 270.289,-1.064 270.289,76.132 211.889,76.132 211.889,105.918
+3.3V_C-V on Bottom Layer "BOTTOM_LAYER_+3.3V_C-V_P504" (solid, remove dead copper, pour order 504): 222.943,16.236 258.067,16.236 258.143,16.313 258.143,22.436 222.943,22.436
GND on Bottom Layer "BOTTOM_LAYER_GND_P464" (solid, remove dead copper, pour order 464): 195.856,37.629 195.856,28.99 197.104,28.99 197.104,37.629
GND_ISO on Bottom Layer "BOTTOM_LAYER_GND_ISO_P458" (solid, pour order 458): -0.2,93.2 16.206,93.2 19.612,89.794 19.612,62.405 17.043,59.836 -0.2,59.836
GND_ISO on Bottom Layer "BOTTOM_LAYER_GND_ISO_P440" (solid, pour order 440): 0.549,89.794 0.549,60.074 0.519,60.044 1.033,59.53 11.838,59.53 12.519,60.212 12.519,66.487 13.863,67.83 17.418,67.83 19.563,69.975 19.463,70.075 19.463,86.03 15.663,89.83
+5V on Bottom Layer "BOTTOM_LAYER_+5V_P365" (solid, remove dead copper, pour order 365): 53.839,28.863 54.351,29.375 57.114,29.375 57.383,29.106 57.383,27.406 57.183,27.206 53.875,27.206 53.839,27.242
+5V on Bottom Layer "BOTTOM_LAYER_+5V_P366" (solid, remove dead copper, pour order 366): 53.625,24.9 53.8,25.075 57.15,25.075 57.35,24.875 57.35,23.175 57.15,22.975 53.825,22.975 53.625,23.175
+3.3V_LDO on Bottom Layer "BOTTOM_LAYER_+3.3V_LDO_P367" (solid, remove dead copper, pour order 367): 57.583,29.106 57.851,29.375 60.614,29.375 60.883,29.106 60.883,27.706 60.383,27.206 57.783,27.206 57.583,27.406
+3.3V_C-V_LDO on Bottom Layer "Bottom Layer-+3.3V_C-V_LDO" (solid, remove dead copper, pour order 370): 60.475,22.85 63.225,22.85 63.225,24.45 62.55,25.125 57.875,25.125 57.525,24.775 57.525,23.1 57.775,22.85
AGND_B on Bottom Layer "BOTTOM_LAYER_AGND_B_P371" (solid, remove dead copper, pour order 371): 38.2,34.65 38.2,38.05 38.5,38.35 39.7,38.35 39.846,38.496 39.846,39.004 38.3,40.55 38.3,41.75 38.5,41.95 42.7,41.95 42.8,42.05 42.8,42.65 41.8,43.65 36.2,43.65 36,43.45 36,34.65 36.2,34.45 38,34.45
AGND_A on Bottom Layer "BOTTOM_LAYER_AGND_A_P381" (solid, remove dead copper, pour order 381): 38.2,51.05 38.2,54.45 38.5,54.75 39.7,54.75 39.846,54.896 39.846,55.404 38.3,56.95 38.3,58.15 38.5,58.35 42.7,58.35 42.8,58.45 42.8,59.05 41.8,60.05 36.2,60.05 36,59.85 36,51.05 36.2,50.85 38,50.85
AGND_C on Bottom Layer "BOTTOM_LAYER_AGND_C_P387" (solid, remove dead copper, pour order 387): 69.9,42.5 69.9,45.9 70.2,46.2 71.4,46.2 71.546,46.346 71.546,46.854 70,48.4 70,49.6 70.2,49.8 74.4,49.8 74.5,49.9 74.5,50.5 73.5,51.5 67.9,51.5 66.9,50.5 66.9,42.9 67.5,42.3 69.7,42.3
GND on Bottom Layer "BOTTOM_LAYER_GND_P394" (solid, remove dead copper, pour order 394): 29.75,48.75 31,47.5 57.25,47.5 61.25,51.5 61.25,59.5 56.75,64 31.85,64 29.75,61.9
GND on Bottom Layer "BOTTOM_LAYER_GND_P395" (solid, remove dead copper, pour order 395): 29.75,32.734 31.884,30.6 56.85,30.6 61.25,35 61.25,43.5 57.25,47.5 31,47.5 29.75,46.25
NetJ100_1 on Bottom Layer "BOTTOM_LAYER_NETJ100_1_P396" (solid, remove dead copper, pour order 396): 6.9,17.7 9,19.8 10.7,19.8 15.1,15.4 15.1,5.6 14,4.5 7.7,4.5 6.9,5.3
GND on Bottom Layer "BOTTOM_LAYER_GND_P397" (solid, remove dead copper, pour order 397): 62.32,39.5 99.25,39.5 100.25,40.5 100.25,57 94.5,62.75 68.75,62.75 62.32,56.32
+3.3V_L on Bottom Layer "BOTTOM_LAYER_+3.3V_L_P402" (solid, remove dead copper, pour order 402): 48.975,24.95 49.175,25.15 52.075,25.15 52.275,24.95 52.275,23.383 51.942,23.05 49.175,23.05 48.975,23.25
+12V_L on Bottom Layer "BOTTOM_LAYER_+12V_L_P403" (solid, remove dead copper, pour order 403): 45.475,24.65 45.675,24.85 48.575,24.85 48.775,24.65 48.775,22.95 48.575,22.75 45.675,22.75 45.475,22.95
+3.3V_H on Bottom Layer "BOTTOM_LAYER_+3.3V_H_P426" (solid, remove dead copper, pour order 426): 48.975,29.25 49.175,29.45 52.075,29.45 52.275,29.25 52.275,27.85 51.775,27.35 49.175,27.35 48.975,27.55
+12V_H on Bottom Layer "BOTTOM_LAYER_+12V_H_P427" (solid, remove dead copper, pour order 427): 45.475,28.95 45.675,29.15 48.575,29.15 48.775,28.95 48.775,27.25 48.575,27.05 45.675,27.05 45.475,27.25
GND on Int2 (PWR) "INT2_(PWR)_GND_P488" (solid, remove dead copper, pour order 488): 0.443,55.536 0.443,-1.364 59.039,-1.364 59.039,24.084 48.843,24.084 48.843,18.236 42.568,11.961 27.543,11.961 27.543,19.936 25.043,22.436 25.043,32.036 28.143,32.036 28.143,57.436 33.043,62.336 27.543,62.336 27.543,59.236 23.843,55.536
GND on Int2 (PWR) "INT2_(PWR)_GND_P486" (solid, remove dead copper, pour order 486): 26.944,91.319 86.443,91.319 94.243,83.519 94.243,62.006 212.557,62.006 222.743,51.819 222.743,25.043 227.343,20.443 227.343,1.136 270.002,1.136 270.002,76.019 211.343,76.019 211.343,105.019 26.944,105.019
GND on Int2 (PWR) "Int2 (PWR)-CARD_VCC" (solid, remove dead copper, pour order 415): 126.25,44.236 204.843,44.236 204.843,39.75 212.5,39.75 212.5,45.232 209.732,48 126.25,48
+5V on Int2 (PWR) "INT2_(PWR)_+5V_P478" (solid, remove dead copper, pour order 478): 93.143,39.836 204.343,39.736 204.343,45.636 201.543,45.636 199.443,43.536 93.143,43.536
+3.3V on Int2 (PWR) "Int2 (PWR)-+3.3V" (solid, remove dead copper, pour order 420): 27.5,61.7 64,61.7 64,30 202.5,30 205.25,30 205.25,39 74.143,39 74.143,66.136 32.823,66.136 32.823,85.25 27.5,85.25 27.5,66.75
GND on Int2 (PWR) "INT2_(PWR)_GND_P421" (solid, remove dead copper, pour order 421): 205.863,29.536 205.863,42.736 212.5,42.736 212.5,18.436 60.943,18.436 60.943,29.536
GND on Int2 (PWR) "INT2_(PWR)_GND_P499" (solid, remove dead copper, pour order 499): 155.043,61.736 155.043,56.436 217.639,56.436 212.324,61.752 212.309,61.736
GND on Int2 (PWR) "INT2_(PWR)_GND_P498" (solid, remove dead copper, pour order 498): 121.238,52.425 121.238,49.536 99.443,49.536 99.443,47.272 74.427,47.272 74.427,59.836 76.327,59.836 76.327,85.086 78.444,85.086 87.433,76.097 87.433,49.884 98.027,49.884 98.027,52.461
GND on Int2 (PWR) "INT2_(PWR)_GND_P497" (solid, remove dead copper, pour order 497): 32.993,85.618 32.993,66.2 66.843,66.2 66.843,85.836 53.588,85.836 53.588,70.493 48.143,70.493 48.143,85.653
+3.3V on Int2 (PWR) "INT2_(PWR)_+3.3V_P494" (solid, remove dead copper, pour order 494): 153.843,74.229 155.618,74.229 155.618,90.844 153.843,90.844
+3.3V on Int2 (PWR) "INT2_(PWR)_+3.3V_P493" (solid, remove dead copper, pour order 493): 66.862,59.966 76.243,59.966 76.243,86.236 66.862,86.236
GND on Int2 (PWR) "INT2_(PWR)_GND_P489" (solid, remove dead copper, pour order 489): 35.324,61.536 35.324,54.782 30.543,54.782 30.543,44.336 33.45,44.336 35.009,42.777 34.875,42.643 34.875,25.136 47.143,25.136 52.588,17.736 63.798,17.736 63.798,61.536
+15V on Int2 (PWR) "Int2 (PWR)-+15V" (solid, remove dead copper, pour order 416): 26.743,90.836 26.743,85.739 48.243,85.739 48.243,70.536 53.543,70.536 53.543,86.136 77.543,86.136 87.5,76.179 87.5,50 97.943,50 97.943,52.5 214,52.5 217.5,49 217.5,24 223,18.5 223,9.25 225,7.25 229.243,7.25 229.755,6.738 229.755,5.318 231.325,5.318 231.325,6.738 231.837,7.25 241.243,7.25 241.755,6.738 241.755,5.318 243.325,5.318 243.325,6.738 243.837,7.25 253.83,7.25 254.158,6.922 254.158,5.318 255.743,5.318 255.743,7.757 253.25,10.25 228,10.25 227.25,11 227.25,20 222.25,25 222.25,51.75 217.75,56.25 94.043,56.25 94.043,83.036 86.243,90.836
+24V_H on Int2 (PWR) "INT2_(PWR)_+24V_H_P485" (solid, remove dead copper, pour order 485): 54.366,57.166 57.343,57.166 57.343,60.836 54.366,60.836
+3.3V_H on Int2 (PWR) "INT2_(PWR)_+3.3V_H_P484" (solid, remove dead copper, pour order 484): 49.743,28.025 52.743,28.025 52.743,29.736 49.743,29.736
+3.3V_C-V on Int2 (PWR) "INT2_(PWR)_+3.3V_C-V_P480" (solid, remove dead copper, pour order 480): 134.258,61.536 134.258,58.536 144.253,58.536 144.253,61.536
+5V on Int2 (PWR) "INT2_(PWR)_+5V_P477" (solid, remove dead copper, pour order 477): 74.943,47.036 74.943,39.836 99.261,39.836 99.261,47.036
+5V on Int2 (PWR) "INT2_(PWR)_+5V_P474" (solid, remove dead copper, pour order 474): 99.443,61.653 99.443,56.836 127.643,56.836 127.643,61.653
-15V on Int2 (PWR) "INT2_(PWR)_-15V_P473" (solid, remove dead copper, pour order 473): 236.443,6.936 236.443,3.236 238.643,3.236 238.643,6.936
-15V on Int2 (PWR) "INT2_(PWR)_-15V_P472" (solid, remove dead copper, pour order 472): 248.843,6.886 248.843,1.636 251.043,1.636 251.043,6.886
GND_ISO on Int2 (PWR) "INT2_(PWR)_GND_ISO_P454" (solid, pour order 454): 0,93 16.4,93 19.812,89.588 19.812,62.605 17.274,60.067 0,60.067
-15V on Int2 (PWR) "Int2 (PWR)--15V" (solid, remove dead copper, pour order 413): 213.328,45.462 213.328,1.236 251.043,1.236 251.043,4.905 227.229,4.905 222.828,8.962 222.828,18.252 217.328,23.752 217.328,48.712 214.078,51.962 121.328,51.962 121.328,49.462 99.543,49.462 99.543,43.962 126.078,43.962 126.078,48.462 210.328,48.462
+12V_L on Int2 (PWR) "INT2_(PWR)_+12V_L_P406" (solid, remove dead copper, pour order 406): 34.808,27.05 34.808,24.997 45.25,24.997 46.25,24.997 46.25,22.747 45.25,22.747 45.25,21.25 40.997,16.997 32.5,16.997 30.5,18.997 30.5,44.047 33.7,44.047 34.808,42.939
+12V_H on Int2 (PWR) "INT2_(PWR)_+12V_H_P410" (solid, remove dead copper, pour order 410): 45.75,21.05 45.75,25.036 47.343,25.036 47.343,27.059 45.5,27.059 45.5,29.5 48.7,29.5 48.7,18.45 42.5,12.25 27.75,12.25 27.75,20 25.25,22.5 25.25,31.75 28.343,31.75 28.343,57.736 31.857,61.25 35.012,61.25 35.012,55 30.25,55 30.25,18.35 32.1,16.5 41.2,16.5
GND on Int3 (GND) "INT3_(GND)_GND_P461" (solid, remove dead copper, pour order 461): 26.643,104.279 26.643,59.267 23.219,55.842 0.039,55.842 0.039,-0.964 50.585,-0.964 50.585,9.888 59.039,18.342 214.039,18.342 219.539,12.842 219.539,3.842 223.039,0.342 270.289,0.342 270.289,76.479 211.889,76.479 211.889,104.279
GND_ISO on Int3 (GND) "INT3_(GND)_GND_ISO_P456" (solid, pour order 456): -0.1,93.4 16.306,93.4 19.712,89.994 19.712,62.605 17.207,60.1 -0.1,60.1
VIN_12V_1 on Int3 (GND) "INT3_(GND)_VIN_12V_1_P453" (solid, remove dead copper, pour order 453): 27,3.9 27.7,4.6 46.2,4.6 47.7,6.1 47.7,15.8 52.9,21 251.5,21 258.6,28.1 258.6,39.3 260.3,41 261.5,41 261.7,40.8 261.7,27 252.734,18.034 55.834,18.034 50.546,12.746 50.546,3.746 46.8,0 29.1,0 27,2.1
GND on Top Layer "TOP_LAYER_GND_P459" (solid, remove dead copper, pour order 459): 26.847,105.918 26.847,60.161 23.423,56.736 0.243,56.736 0.243,-4.464 50.789,-4.464 50.789,10.782 58.041,18.034 215.446,18.034 219.743,13.736 219.743,-0.864 269.55,-0.864 269.55,75.236 211.743,75.236 211.743,105.918
GNDP on Top Layer "TOP_LAYER_GNDP_P501" (solid, remove dead copper, pour order 501): 32.706,72.576 32.706,74.75 30.693,76.763 27.443,76.763 27.443,72.576
GNDP1 on Top Layer "TOP_LAYER_GNDP1_P500" (solid, remove dead copper, pour order 500): 206.143,101.155 206.143,98.036 206.843,97.336 211.2,97.336 211.2,101.203 211.153,101.155
-15V on Top Layer "TOP_LAYER_-15V_P375" (solid, remove dead copper, pour order 375): 87.4,43.3 87.9,43.8 96,43.8 98.75,43.8 100,45 100,47.9 105.643,47.9 105.643,46.639 92.993,34.01 93,31.7 92.8,31.5 87.6,31.5 87.4,31.7
+24V_L on Top Layer "TOP_LAYER_+24V_L_P470" (solid, remove dead copper, pour order 470): 62.143,39.041 65.343,39.041 65.343,35.436 62.143,35.436
GND on Top Layer "TOP_LAYER_GND_P467" (solid, remove dead copper, pour order 467): 29.768,48.757 31.018,47.507 57.268,47.507 61.268,51.507 61.268,59.507 56.768,64.007 31.268,64.007 29.768,62.507
GND on Top Layer "TOP_LAYER_GND_P466" (solid, remove dead copper, pour order 466): 187.043,44.236 187.043,42.736 195.943,42.736 195.943,44.236
+5V on Top Layer "TOP_LAYER_+5V_P463" (solid, remove dead copper, pour order 463): 195.856,37.629 195.856,28.99 197.104,28.99 197.104,37.629
GND_ISO on Top Layer "TOP_LAYER_GND_ISO_P452" (solid, pour order 452): 0,93 16.406,93 19.812,89.594 19.812,61.763 18.149,60.1 0,60.1
GND on Top Layer "TOP_LAYER_GND_P449" (solid, remove dead copper, pour order 449): 29.692,32.709 31.826,30.575 56.192,30.575 61.192,35.575 61.192,43.475 57.192,47.475 30.942,47.475 29.692,46.225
